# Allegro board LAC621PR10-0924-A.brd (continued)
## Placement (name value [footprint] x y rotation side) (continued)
RL34  -  [R0402_0OHM]  257.77 83.57 90 top
RL70  -  [R_0402]  261.12 90.07 270 bottom
RL71  -  [R_0603]  261.68 80.3 270 top
RL72  -  [R_0603]  263.03 80.32 270 top
RL73  -  [R_0603]  264.4 80.32 270 top
RL74  -  [R_0603]  265.8 80.34 270 top
RL75  -  [R_0603]  267.17 80.32 270 top
RL76  -  [R_0603]  268.54 80.32 270 top
RL77  -  [R_0603]  269.12 81.46 0 top
RL78  -  [R_0603]  269.12 82.86 0 top
RN1  -  [R_0402]  278.6 20.02 0 top
RN2  -  [R_0402]  281.93 16.72 180 top
RN5  -  [R_0402]  275.35 18.75 0 top
RN6  -  [R_0402]  265.27 34.03 180 top
RN7  -  [R_0402]  264.36 33.14 0 top
RN8  -  [R_0402]  266.74 20.4 180 top
RN9  -  [R_0402]  266.74 21.29 180 top
RN10  -  [R_0402]  265.82 18.62 0 top
RN11  -  [R_0402]  266.74 19.51 180 top
RN12  -  [R_0402]  261.87 30.21 90 top
RN13  -  [R_0402]  261.87 28.18 90 top
RN14  -  [R_0402]  259.91 31.12 270 top
RN16  -  [R_0402]  259.91 28.18 90 top
RN18  -  [R_0402]  264.37 17.66 90 top
RN19  -  [R_0402]  263.49 17.66 90 top
RN20  -  [R_0402]  262.88 31.12 270 top
RN21  -  [R_0402]  262.88 28.18 90 top
RN22  -  [R_0402]  275.35 19.64 0 top
RN23  -  [R_0402]  277.14 19.31 270 top
RN25  -  [R_0402]  228.05 37.72 90 top
RN26  -  [R_0402]  224.42 31.88 0 top
RN27  -  [R_0402]  225.23 25.13 90 top
RN28  -  [R_0402]  222.64 30.05 0 top
RN30  -  [R_0402]  225.31 29.14 180 top
RN31  -  [R_0402]  237.12 29.02 180 top
RN37  -  [R_0402]  255.79 11.07 0 top
RN38  -  [R_0402]  227.16 34.29 90 top
RN39  -  [R_0402]  225.31 30.97 180 top
RN40  -  [R_0402]  226.12 26.04 270 top
RN41  -  [R_0402]  225.31 30.03 180 top
RN42  -  [R_0402]  235.04 31.65 270 top
RN43  -  [R_0402]  233.97 29.04 180 top
RN44  -  [R_0402]  233.36 25.13 90 top
RN45  -  [R_0402]  233.06 30.81 0 top
RN46  -  [R_0402]  233.06 29.93 0 top
RN47  -  [R_0402]  232.47 26.04 270 top
RN49  -  [R_0402]  223.48 28.48 270 top
RN50  -  [R_0402]  233.97 27.26 180 top
RN51  -  [R_0402]  228.79 25.13 90 top
RN52  -  [R_0402]  225.31 28.2 180 top
RN53  -  [R_0402]  233.06 28.15 0 top
RN54  -  [R_0402]  229.67 26.04 270 top
RN55  -  [R_0402]  237.7 34.07 270 top
RN56  -  [R_0402]  235.95 31.68 0 top
RN57  -  [R_0402]  237.17 24.11 90 top
RN58  -  [R_0402]  236.2 30.79 0 top
RN59  -  [R_0402]  238.59 33.15 90 top
RN60  -  [R_0402]  236.82 33.15 90 top
RN61  -  [R_0402]  238.31 25.03 270 top
RN62  -  [R_0402]  237.12 29.9 180 top
RN63  -  [R_0402]  244.84 32.32 0 top
RN64  -  [R_0402]  245.75 29.65 180 top
RN65  -  [R_0402]  244.84 25.97 0 top
RN66  -  [R_0402]  244.84 31.43 0 top
RN67  -  [R_0402]  244.84 30.54 0 top
RN68  -  [R_0402]  244.84 26.86 0 top
RN69  -  [R_0402]  236.2 27.24 0 top
RN70  -  [R_0402]  245.75 28.76 180 top
RN71  -  [R_0402]  241.87 24.11 90 top
RN72  -  [R_0402]  237.12 28.13 180 top
RN73  -  [R_0402]  244.84 27.87 0 top
RN74  -  [R_0402]  240.98 25.03 270 top
RN77  -  [R_0402]  227.01 25.13 90 top
RN78  -  [R_0402]  227.9 25.13 90 top
RN81  -  [R_0402]  239.2 24.11 90 top
RN82  -  [R_0402]  240.09 24.11 90 top
RN83  -  [R_0402]  260.87 29.11 270 top
RN84  -  [R_0402]  260.98 31.12 270 top
RN99  -  [R0402_0OHM]  249.82 10.75 0 top
RPC1  -  [RP_0804_8P4R]  194.89 65.04 90 bottom
RPC2  -  [RP_0804_8P4R]  192.51 52.21 90 top
RPC3  -  [RP_0804_8P4R]  175.97 82.56 90 bottom
RPC4  -  [RP_0804_8P4R]  184.17 72.38 270 bottom
RPC5  -  [RP_0804_8P4R]  183.91 69.52 180 bottom
RPE2  -  [RP_0804_8P4R]  258.91 70.31 270 top
RPE3  -  [RP_0804_8P4R]  259.12 49.51 270 top
RPE5  -  [RP_0804_8P4R]  277.61 59.23 0 top
RPE7  -  [RP_0804_8P4R]  296.52 41.62 180 top
RPE8  -  [RP_0804_8P4R]  242.09 82.64 180 top
RPE9  -  [RP_0804_8P4R]  253.69 73.55 270 top
RPE10  -  [RP_0804_8P4R]  277.61 62.15 0 top
RPE11  -  [RP_0804_8P4R]  242.4 74.5 0 top
RPE12  -  [RP_0804_8P4R]  263.87 75.65 270 top
RPE13  -  [RP_0804_8P4R]  264.09 48.14 90 top
RPV1  -  [RP_0804_8P4R]  223.93 95.05 0 top
RPV2  -  [RP_0804_8P4R]  205.73 87.63 180 top
RR1  -  [R_0402]  259.8 37.88 270 top
RR16  -  [R_0402]  267.3 41.61 180 top
RR17  -  [R0402_0OHM]  262.47 37.88 270 top
RR18  -  [R0402_0OHM]  263.36 37.88 270 top
RR19  -  [R_0402]  267.3 42.5 180 top
RR20  -  [R_0402]  259.17 45.47 90 top
RR21  -  [R0402_0OHM]  258.86 38.69 180 top
RR22  -  [R0402_0OHM]  258.86 37.8 180 top
RR23  -  [R0402_0OHM]  261.58 37.88 270 top
RV1  -  [R_0402]  86.42 85.91 90 top
RV2  -  [R_0402]  85.56 85.91 90 top
RV3  -  [R_0402]  99.02 82.1 270 bottom
RV4  -  [R_0402]  88.89 79.15 0 bottom
RV5  -  [R_0402]  91.55 80.09 270 bottom
RV6  -  [R_0402]  96.35 98.17 90 top
RV8  -  [R_0402]  93.15 98.94 270 top
RV10  -  [R_0402]  81.32 95.65 180 top
RV11  -  [R_0402]  82.18 95.65 0 top
RV12  -  [R_0402]  84.16 94.75 180 top
RV13  -  [R_0402]  85.03 94.75 0 top
RV14  -  [R_0402]  89.65 94.72 180 top
RV15  -  [R_0402]  90.51 94.72 0 top
RV16  -  [R_0402]  86.91 95.61 180 top
RV17  -  [R_0402]  87.77 95.61 0 top
RV18  -  [R_0402]  106.06 94.59 180 bottom
RV19  -  [R_0402]  78.95 99.09 270 top
RV20  -  [R_0402]  94.53 99.22 0 top
RV21  -  [R_0402]  106.08 95.53 180 bottom
RV22  -  [R_0402]  91.38 93.82 0 top
RV32  -  [R_0402]  232.8 94.67 180 bottom
RV33  -  [R_0402]  234.3 94.67 0 bottom
RV34  -  [R_0402]  236.71 94.55 0 bottom
RV35  -  [R_0402]  236.36 103.2 0 bottom
RV36  -  [R_0402]  247.15 103.18 180 bottom
RV37  -  [R_0402]  242.66 100.84 90 bottom
RV38  -  [R_0402]  240.88 100.84 90 bottom
RV73  -  [R_0402]  228.99 84.61 0 top
RV74  -  [R_0402]  210.15 92.89 0 top
RV75  -  [R_0402]  217.92 94.68 180 bottom
RV76  -  [R_0402]  231.66 88.19 270 top
RV77  -  [R_0402]  232.55 88.19 270 top
RV78  -  [R_0402]  234.73 88.24 270 top
RV79  -  [R_0402]  210.98 84.41 180 top
RV80  -  [R_0402]  223.3 82.42 90 top
RV81  -  [R_0402]  223.3 85.09 270 top
RV82  -  [R_0402]  220.1 94.7 0 bottom
RV83  -  [R_0402]  212.74 82.58 270 top
RV84  -  [R_0402]  210.98 83.49 180 top
RV85  -  [R_0402]  209.28 92.89 180 top
RV86  -  [R_0402]  206.97 92.23 270 top
RV87  -  [R_0402]  207.17 90.4 0 bottom
RV88  -  [R_0402]  229.91 85.5 180 top
RV89  -  [R_0402]  229.51 87.32 0 top
RV90  -  [R_0402]  125.31 89.41 180 bottom
RV91  -  [R_0402]  146.31 92.13 180 bottom
RV121  -  [R_0402]  235.62 87.33 90 top
RV250  -  [R_0402]  236.51 87.33 90 top
RV251  -  [R_0402]  238.11 87.33 90 top
RV508  -  [R_0402]  132.75 92.13 180 bottom
RV509  -  [R_0402]  141.49 87.46 0 bottom
RV516  -  [R_0402]  208.44 84.54 180 top
RV517  -  [R_0402]  208.32 83.49 0 top
RV518  -  [R_0402]  210.4 96.78 0 top
RV519  -  [R_0402]  210.41 95.91 0 top
RV600  -  [R_0402]  201.56 89.54 180 bottom
RV601  -  [R_0402]  186.83 88.6 0 bottom
RV602  -  [R_0402]  199.86 91.32 270 bottom
RV603  -  [R_0402]  186.32 90.63 0 bottom
RV604  -  [R_0402]  201.89 83.65 180 bottom
RV605  -  [R_0402]  201.94 81.39 180 bottom
RV606  -  [R_0402]  193.31 80.57 90 bottom
RV607  -  [R_0402]  199.05 79.85 180 bottom
RV608  -  [R_0402]  201.89 84.76 180 bottom
RV609  -  [R_0402]  201.89 82.73 180 bottom
RV610  -  [R_0402]  191.02 94.3 270 bottom
RV611  -  [R_0402]  185.08 85.15 0 bottom
RV612  -  [R_0402]  185.08 86.04 0 bottom
RV613  -  [R_0402]  185.08 87.18 0 bottom
RV614  -  [R_0402]  185.08 88.07 0 bottom
RV615  -  [R_0402]  186.32 89.62 0 bottom
RV616  -  [R_0402]  192.67 90.44 90 bottom
RV617  -  [R_0402]  186.86 84.64 0 bottom
RV618  -  [R_0402]  186.86 85.53 0 bottom
RV619  -  [R_0402]  186.86 86.67 0 bottom
RV620  -  [R_0402]  186.86 87.56 0 bottom
RV621  -  [R_0402]  187.24 91.52 180 bottom
RV623  -  [R_0402]  82.76 83.06 90 bottom
RV647  -  [R_0402]  81.27 97.09 90 top
RV648  -  [R_0402]  82.19 99.18 180 top
RV649  -  [R_0402]  82.13 97.09 90 top
RV650  -  [R_0402]  84.12 97.07 90 top
RV651  -  [R_0402]  85 99.18 180 top
RV652  -  [R_0402]  84.98 97.07 90 top
RV653  -  [R_0402]  89.63 97.02 90 top
RV654  -  [R_0402]  90.47 99.18 180 top
RV655  -  [R_0402]  90.49 97.02 90 top
RV656  -  [R_0402]  86.93 97.04 90 top
RV657  -  [R_0402]  87.82 99.18 180 top
RV658  -  [R_0402]  87.8 97.04 90 top
RV659  -  [R_0402]  234.66 96.57 180 top
RV660  -  [R_0402]  233.75 97.46 0 top
RV661  -  [R_0402]  234.67 95.66 180 top
RV662  -  [R0402_0OHM]  227.18 94.55 90 top
RZ8  -  [R_0402]  266.79 13.8 0 top
RZ9  -  [R_0402]  266.79 12.91 0 top
RZ10  -  [R_0402]  260.56 12.35 270 top
RZ18  -  [R_0402]  220.47 35.9 180 top
RZ19  -  [R_0402]  220.47 35.02 180 top
RZ20  -  [R_0402]  221.11 32.59 180 top
RZ21  -  [R_0402]  220.29 34.15 180 top
RZ22  -  [R0402_0OHM]  217.5 36.78 0 top
RZ23  -  [R0402_0OHM]  217.43 35.73 0 top
RZ24  -  [R_0402]  287.47 71.09 180 bottom
RZ25  -  [R_0402]  264.76 54.44 270 top
RZ26  -  [R_0402]  220.21 31.66 0 top
RZ27  -  [R_0402]  284.49 75.9 0 bottom
RZ28  -  [R_0402]  275.2 58.42 180 top
RZ29  -  [R_0402]  217.51 33.5 0 top
RZ32  -  [R_0402]  288.33 71.08 0 bottom
RZ34  -  [R_0402]  288.81 66.88 180 bottom
RZ38  -  [R_0402]  252.69 42.88 180 top
RZ40  -  [R_0402]  247.23 47.07 90 top
RZ43  -  [R0402_0OHM]  241.11 76.15 0 top
RZ56  -  [R0402_0OHM]  257.01 19.64 90 top
RZ58  -  [R_0402]  186.86 74.44 270 top
RZ59  -  [R_0402]  189.19 75.31 90 top
RZ60  -  [R_0402]  190.97 75.21 270 top
RZ61  -  [R0402_0OHM]  189.3 72.74 270 top
RZ62  -  [R_0402]  185.76 68.99 90 top
RZ63  -  [R_0402]  190.08 75.21 270 top
RZ64  -  [R0402_0OHM]  246.29 45.42 180 top
RZ65  -  [R_0402]  246.29 46.31 180 top
RZ69  -  [R_0402]  194.91 76.47 180 top
RZ70  -  [R0402_0OHM]  251.04 41.81 270 top
RZ71  -  [R_0402]  250.15 41.81 270 top
RZ72  -  [R_0603]  188.92 61.28 90 top
RZ76  -  [R_0402]  237.32 68.03 0 top
RZ77  -  [R_0402]  237.32 67.14 0 top
RZ78  -  [R_0402]  257.9 19.69 90 top
RZ79  -  [R_0402]  258.79 19.69 90 top
RZ80  -  [R_0402]  258.06 29.09 270 top
RZ81  -  [R_0402]  258.95 29.09 270 top
RZ82  -  [R_0402]  173.54 90.63 0 bottom
RZ83  -  [R_0402]  173.54 91.52 0 bottom
RZ84  -  [R_0402]  272.96 10.75 180 top
RZ85  -  [R0402_0OHM]  275.14 10.77 180 top
RZ86  -  [R0402_0OHM]  263.52 11.67 270 top
RZ87  -  [R_0402]  257.8 15.31 180 top
RZ88  -  [R_0402]  190.82 63.52 0 top
RZ89  -  [R0402_0OHM]  192.09 61.66 180 top
RZ90  -  [R_0402]  185.13 67.76 270 top
RZ110  -  [R_0402]  196.74 68.24 270 top
RZ111  -  [R_0402]  193.64 61.99 270 top
RZ112  -  [R0402_0OHM]  185.68 65.96 180 top
RZ113  -  [R_0402]  196 66.12 270 top
RZ114  -  [R_0402]  263.66 15.18 90 top
RZ115  -  [R_0402]  262.77 15.18 90 top
RZ116  -  [R_0402]  218.44 31.68 0 top
RZ117  -  [R_0402]  218.43 32.57 180 top
RZ118  -  [R0402_0OHM]  266.98 16.39 270 top
RZ119  -  [R_0603]  157.88 42.22 0 top
RZ120  -  [R_0402]  163.06 38.11 180 top
SW1  -  [SW_SS3-CMFTQR9_3P]  247.51 97.44 270 bottom
SW3  -  [SW_SKRBAAE010_4P]  300 84.76 0 top
T1  -  [TPC12]  146.47 85.33 0 top
T2  -  [TPC12]  146.5 72.58 0 top
T3  -  [TPC12]  140.6 59.19 0 top
T4  -  [TPC12]  139.56 45.24 0 top
T5  -  [TPC12]  143.02 61.05 0 top
T6  -  [TPC12]  143.27 59.59 0 top
T9  -  [TPC12]  121.38 87.19 180 bottom
T10  -  [TPC12]  142.51 81.68 180 bottom
T11  -  [TPC12]  140.76 81.83 180 bottom
T12  -  [TPC12]  122.49 44.39 0 top
T13  -  [TPC12]  124.14 44.43 0 top
T14  -  [TPC12]  166.07 61.68 0 top
T15  -  [TPC12]  168.46 62.14 0 top
T16  -  [TPC12]  125.28 45.19 0 top
T17  -  [TPC12]  129 45.96 0 top
T50  -  [TPC12]  120.81 14.51 0 top
T51  -  [TPC12]  123.28 15.45 0 top
T54  -  [TPC12]  203.19 14.75 0 top
T55  -  [TPC12]  201.89 15.27 0 top
T87  -  [TPC12]  233.82 103.29 180 bottom
T88  -  [TPC12]  268.6 84.27 0 top
T89  -  [TPC12]  268.6 86.35 0 top
T97  -  [TPC12]  246.37 84.69 180 bottom
T98  -  [TPC12]  252.77 90.8 0 top
T99  -  [TPC12]  246.34 89.23 0 top
T108  -  [TPC12]  229.1 88.74 0 top
T113  -  [TPC12]  126.33 46.04 0 top
T114  -  [TPC12]  127.68 45.99 0 top
T115  -  [TPC12]  167.98 59.57 0 top
T120  -  [TPC12]  166.76 70.26 0 top
T121  -  [TPC12]  180.79 45.63 0 top
T122  -  [TPC12]  156.3 69.73 0 top
T123  -  [TPC12]  155.73 63.2 0 top
T126  -  [TPC12]  191 49.19 180 bottom
T127  -  [TPC12]  193.25 49.1 180 bottom
T128  -  [TPC12]  180.15 57.86 180 bottom
T129  -  [TPC12]  178.5 58.33 180 bottom
T130  -  [TPC12]  182.11 46.24 90 top
T131  -  [TPC12]  273.09 60.63 0 top
T132  -  [TPC12]  130.49 46.08 0 top
TL1  -  [MHPC_NS692417_24P]  279.99 85.81 180 bottom
UA1  -  [ALC3235-CG_MQFN48_6X6]  276.06 35.68 270 top
UC1  -  [SKL-U_BGA_1356P-T]  173.35 77.16 0 bottom
UC5  -  [W25Q128FVSIQ_SO8]  191.1 75.46 0 bottom
UC6  -  [W25Q64FVSSIQ_SO8]  191.1 59.97 0 bottom
UC7  -  [TC7SH08FU_SSOP5]  187.65 67.94 270 bottom
UC8  -  [74CBTLV3126BQ_DHVQFN14_2P5X3]  99.2 42.57 0 top
UC12  -  [74AHC1G09GW_TSSOP5]  180.06 90.08 0 bottom
UC13  -  [TC7SH08FU_SSOP5]  172.2 92.26 270 bottom
UC14  -  [TC7SH08FU_SSOP5]  188.31 30.3 0 top
UD1  -  [74AUP1G07GW_TSSOP5]  77.43 13.9 180 top
UE1  -  [ECE5048-LZY_DQFN132_11X11]  253.39 88.08 180 top
UE2  -  [MEC5085-LZY_DQFN132_11X11]  271.35 57.54 90 top
UE3  -  [TC7SH08FU_SSOP5]  227.22 76.57 0 top
UE4  -  [74AUP1G07GW_TSSOP5]  225.92 79.09 180 top
UE5  -  [TC7SH08FU_SSOP5]  254.72 64.99 0 top
UI1  -  [SY6288D20AAC_SOT23-5]  19.38 90.59 0 bottom
UI2  -  [SY6288D20AAC_SOT23-5]  72.48 92.41 180 top
UI3  -  [PI5USB2544ZHEX_TQFN16_3X3]  281.49 64.33 0 top
UL1  -  [WGI217LM-QPN9-A2_QFN48_6X6]  261.12 89.13 270 top
UL2  -  [TC7SH08FU_SSOP5]  282.51 73.06 180 bottom
UL4  -  [PI3L720ZHEX_TQFN42_9X3P5]  273.42 82.72 270 top
UN1  -  [LNG2DMTR_LGA12_2X2]  252.69 32.59 0 top
UN4  -  [PS8558BTQFN24GTR2-A_TQFN24_4X4]  230.54 32.21 270 top
UN5  -  [PS8558BTQFN24GTR2-A_TQFN24_4X4]  241.87 31.17 270 top
UN7  -  [PI3EQX6741STZDEX_TQFN20_4X4]  260.15 25.44 0 top
UR2  -  [RTS5242-GR_QFN32_4X4]  263.92 43.69 270 top
UV2  -  [AP2330W-7_SC59-3]  103.01 94.03 0 bottom
UV4  -  [AP2330W-7_SC59-3]  244.51 100.41 270 bottom
UV8  -  [VMM3320BJGR_BGA_168P-NH]  213.91 85.24 90 top
UV9  -  [W25X10BVSNIG_SO8]  211.46 88.09 270 bottom
UV11  -  [PI3C3125LEX_TSSOP14]  121.34 90.69 90 bottom
UV12  -  [PI3C3125LEX_TSSOP14]  147.98 84.66 180 bottom
UV16  -  [PI3V713-AZLEX_TQFN32_6X3]  233.01 90.04 0 top
UV24  -  [G524B1T11U_SOT23-5]  94.91 81.45 0 bottom
UV26  -  [PS8338BQFN60GTR-A0_QFN60_5X9]  190.65 88.01 0 bottom
UV28  -  [TPS22961DNYR_WSON8]  227.19 95.18 0 bottom
UV29  -  [APL5930QBI-TRG_TDFN10_3X3]  232.16 95.75 90 top
UZ2  -  [TPS22966DPUR_SON14_2X3]  246.66 49.22 0 top
UZ3  -  [TPS22966DPUR_SON14_2X3]  251.22 39.26 180 top
UZ4  -  [TPS22966DPUR_SON14_2X3]  243.94 45.24 90 top
UZ5  -  [TPS22966DPUR_SON14_2X3]  273.99 44.92 0 top
UZ6  -  [TC7SH08FU_SSOP5]  220.62 29.28 90 top
UZ8  -  [AOZ1336_DFN8_2X2]  248.8 45.06 180 top
UZ10  -  [TC7SH08FU_SSOP5]  288.81 65.51 180 top
UZ12  -  [NPCT650JAAYX_QFN32_5X5]  187.9 64.87 90 top
UZ19  -  [TPS22961DNYR_WSON8]  167.68 93 270 bottom
UZ20  -  [TPS22961DNYR_WSON8]  168.81 86.7 90 bottom
UZ21  -  [TPS22961DNYR_WSON8]  165.36 88.55 0 bottom
UZ23  -  [AOZ1336_DFN8_2X2]  265.54 31.82 180 top
UZ26  -  [TPS22961DNYR_WSON8]  159.03 38.23 0 top
YC1  -  [Y_X3G024000DC1H_4P]  154.22 84.32 180 bottom
YC2  -  [Y_9H03200042_2P]  182.79 61.98 270 bottom
YE1  -  [Y_Q13FC135000040_2P]  266.54 51.22 0 top
YL1  -  [Y_7V25000034_4P]  259.48 79.94 90 top
YV2  -  [Y_X1E000021042600_4P]  227.01 82.42 90 top

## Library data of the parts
C33 CC210 CC219-CC221 CC225 CC226 CC271-CC274 CL28 PC5 PC7 PC104-PC110 PC117 PC118 PC120-PC124 PC201 PC202 PC305 PC306 PC308-PC311 PC508 PC511 PC608 PC612 PC656-PC658 PC672 PC673 PC801 PC803-PC807 PC811 PC812 PC814 PC818-PC820 PC822 PC826 PC827 PC902 PC1501 PC1503 = C_0805
C42 C43 C263 C294-C316 C319 CA1-CA6 CA12 CA13 CA19 CA22-CA24 CA27 CA28 CA33 CA35 CA41 CA54 CC3-CC8 CC21-CC27 CC32 CC33 CC174-CC179 CC181 CC182 CC185 CC186 CC194 CC195 CC199 CC202-CC204 CC206 CC208 CC209 CC211-CC213 CC215-CC218 CC222 CC224 CC248-CC257 CC264 CC266 CC269 CC288 CC297 CC300-CC302 CC310 CC311 CD2-CD4 CD6-CD11 CD24-CD27 CD31 CD35-CD44 CD54 CD57-CD60 CD63 CD70 CD71 CD74 CD75 CD78-CD85 CD102-CD109 CE8-CE10 CE12 CE14 CE15 CE24 CE26-CE30 CE34-CE40 CE44-CE47 CE52 CE53 CI4 CI5 CI13 CI16 CI27-CI31 CI33-CI35 CL1 CL2 CL5 CL6 CL13 CL14 CL18 CN13 CN17 CN18 CN20-CN26 CN30-CN36 CN43-CN48 CN50 CR23-CR27 CR35 CR37 CR42 CR43 CV1-CV6 CV10 CV11 CV13 CV14 CV17 CV18 CV21 CV22 CV28 CV29 CV50-CV59 CV79 CV80 CV85 CV86 CV89 CV92 CV93 CV96-CV99 CV102-CV111 CV113 CV115 CV119 CV120 CV122 CV123 CV127 CV128 CV145-CV150 CV152 CV153 CV156 CV157 CV374 CV603-CV613 CV616 CV619 CZ13 CZ14 CZ16 CZ20-CZ23 CZ30 CZ31 CZ37 CZ38 CZ42 CZ45 CZ46 CZ51-CZ53 CZ55 CZ58 CZ59 CZ65-CZ69 CZ77 CZ84 CZ87 CZ90 CZ91 CZ95 CZ100 CZ105 CZ106 CZ113 PC3 PC4 PC8 PC100 PC101 PC103 PC113 PC115 PC116 PC127 PC128 PC203 PC204 PC210 PC212-PC214 PC301 PC303 PC307 PC401 PC402 PC408-PC411 PC417-PC420 PC503 PC505-PC507 PC509 PC510 PC601 PC602 PC605 PC613 PC614 PC616-PC621 PC624-PC633 PC636 PC637 PC639-PC647 PC649-PC654 PC659-PC661 PC677 PC679 PC680 PC685 PC686 PC688 PC809 PC810 PC815-PC817 PC823 PC824 PC829-PC831 PC833 PC834 PC901 PC903-PC905 PC1500 PC1502 PC1504 = C_0402
C317 C318 CA9 CA10 CA16 CA18 CA25 CA26 CA29 CA31 CA43 CA44 CA46 CA48 CA49 CA51-CA53 CC279 CC280 CC282-CC287 CC294-CC296 CD12-CD19 CD28 CD29 CD45-CD52 CD61 CD62 CD72 CD73 CD76 CD77 CD86-CD101 CE1 CE7 CE21 CE31 CE32 CI6 CI11 CL4 CL12 CN1 CR9 CR38 CR40 CV7 CV9 CV12 CV27 CV82 CV87 CV90 CV94 CV101 CV617 CV618 CZ19 CZ54 CZ60 CZ61 CZ72 CZ76 PC1 PC2 PC6 PC102 PC111 PC112 PC114 PC119 PC125 PC126 PC205-PC207 PC209 PC211 PC215-PC220 PC302 PC304 PC312 PC313 PC403 PC404 PC406 PC407 PC412 PC413 PC415 PC416 PC422 PC424 PC501 PC502 PC504 PC603 PC604 PC611 PC622 PC655 PC662 PC671 PC678 PC802 PC808 PC813 PC821 PC825 PC828 PC832 PC906-PC908 PC1001-PC1029 PC1057-PC1061 PC1064-PC1082 PC1129-PC1146 PC1170-PC1181 = C_0603
CA7 CA8 CA11 CA17 CA45 CA47 CA50 CC9 CC10 CC28-CC30 CC214 CC223 CC270 CC281 CD30 CD32 CD64 CE2-CE6 CE11 CE13 CE16-CE20 CE22 CE23 CE25 CI3 CI7 CI10 CI12 CI17 CI19 CL3 CL7-CL11 CL15-CL17 CL19-CL21 CL25-CL27 CN2 CN14-CN16 CN19 CN29 CN41 CN42 CN49 CR8 CR10 CR13 CR36 CR39 CR41 CV8 CV23 CV26 CV83 CV84 CV88 CV91 CV95 CV100 CV114 CV118 CV121 CV124-CV126 CV144 CV600-CV602 CV615 CZ1 CZ2 CZ10-CZ12 CZ15 CZ17 CZ18 CZ24 CZ27-CZ29 CZ34 CZ36 CZ39 CZ43 CZ44 CZ47 CZ48 CZ50 CZ64 CZ71 CZ73-CZ75 CZ78 CZ82 CZ85 CZ89 CZ92 CZ94 CZ99 CZ114 CZ115 PC1030-PC1056 PC1083-PC1099 PC1125 PC1126 PC1147-PC1153 PC1164 = C_0201
CD20 CD53 = C_D3
CI1 CI8 CI14 = C_1206
CI32 = C_B2-NPM
CL22 = C_1808
CMOS1 = SHORTPADS-NPM: User Part Number: PART#
CZ57 = C_B2
D19 DA4 DA5 DE1 DZ1-DZ7 = RB751S40T1G_SOD523-2
D20 = L30ESD24VC3-2_SOT23-3
DA1-DA3 DA6 DA7 = L03ESDL5V0CC3-2_SOT23-3
DI1 DI4 DI6 = L05ESDL5V0NA-4_SLP2510P8-10-9
DI2 DI3 DI5 DV4 = AZC199-02SPR7G_SOT23-3
DV1-DV3 PD901 PD905 = BAT54CW_SOT323-3
DV5 DV6 = PJDLC05C_SOT23-3
FD1-FD4 = FIDUCIAL_C40M80
H1-H4 H25 = H_3P8
H5 = H_2P6N
H6 = H_3P0X2P0N
H7 H8 = H_3P2
H9 = H_0P9N
H10 = H_0P8N
H11-H22 H24 = H_2P4
H23 = H_3P3
JAPS1 = ACES_50506-01841-P01_18P-NPM
JCRT1 = FUTUR_061-D531-0207_15P
JDEG1 JLPDE1 = HB_A531015-SCHR21_10P
JDIMM1 JDIMM2 = LOTES_ADDR0107-P005A_260P-T
JDOCK1 = JAE_WD2F144WB5R400_144P
JEDP1 = ACES_50398-04041-001_40P
JFAN1 JSPK1 = ACES_50271-0040N-001_4P
JHDMI1 = CONCR_099BKAC19YBLCNF_19P
JHP1 = SINGA_2SJ3095-022111F_6P-T
JIR1 = ACES_50450-0067N-P01_6P
JKBTP1 = ACES_50506-02041-P01_20P
JLED1 = ACES_50506-00841-P01_8P
JLOM1 = SANTA_130456-511_13P-T
JNGFF1 = BELLW_80148-4221_67P
JNGFF2 = BELLW_80149-4221_67P
JNGFF3 = BELLW_SD-80159-4221_67P-T
JRTC1 = ACES_50271-0020N-001_2P
JSATA1 = STARC_115B20-100020-G2-R_20P
JSD1 = T-SOL_156-2000302608_19P_NR
JSIM1 = T-SOL_5-991503004000-6_8P-T
JSPI1 = E-T_6705K-Y20N-00L_20P
JTAG1 = SHORTPADS: User Part Number: PART#
JUART1 = ACES_50207-00471-P01_4P-T
JUSB1 = LOTES_AUSB0014-P003A_9P
JUSB2 = ACON_TARAV-9R1U91_9P
JUSB3 = SINGA_2UB4008-900101F_9P
JUSH1 = E-T_6705K-Y26N-00L_26P
JXDP1 = SAMTE_BSH-030-01-L-D-A_60P
LA2 LA3 = MURAT_BLM15BD601SN1D_2P
LA5 LC1 LC2 = MURAT_BLM15PX600SN1D_2P
LA6-LA11 = MURAT_BLM15PX330SN1D_2P
LED3 = LED_LTW-C193DC-C_2P
LI3 LI4 LI7 LV27 LZ1 = INPAQ_MCM1012B900F06BP_4P
LL1 = TAIYO_BRC2012T4R7MD_2P
LV1 = MURAT_BLM15BB221SN1D_2P
LV16-LV18 = MURAT_BLM15BB470SN1D_2P
LV19 LV20 = MURAT_BLM15AG121SN1D_L0402_2P
LV22-LV25 = MURAT_BLM15PX181SN1D_2P
PBATT1 = DEREN_40-42251-01001RHF_10P-T
PC606 = C_D
PC1062 PC1063 PC1127 PC1128 = C_D2
PD1 = DB3J315E0L_SMINI3-F2-B3
PD2 PD3 = TVNST52302AB0_SOT523-3
PD4 = RB751V-40_SOD323-2
PD6 PD7 = PESD5V0U2BT_SOT23-3
PD801-PD803 PD904 = SDMK0340L-7-F_SOD323-2
PD902 PD903 = PDS5100H-13_POWERDI5-3
PH601-PH605 PR1-PR3 PR5-PR12 PR14 PR15 PR101-PR103 PR107-PR110 PR113 PR115-PR118 PR203 PR206 PR207 PR209 PR302 PR306-PR308 PR310 PR311 PR403 PR404 PR407 PR408 PR410 PR411 PR413-PR421 PR424-PR426 PR428 PR501 PR505-PR511 PR601 PR604 PR605 PR608 PR610-PR613 PR617 PR618 PR621-PR623 PR626 PR628-PR633 PR635 PR636 PR638-PR652 PR656 PR657 PR662 PR678 PR680 PR801 PR803 PR805 PR808 PR809 PR812 PR813 PR817 PR818 PR821 PR822 PR825 PR827 PR829-PR832 PR834 PR837 PR902-PR905 PR908-PR912 PR914-PR917 PR920 PR925 PR927 PR929 PR934 PR936 PR1500-PR1503 R6 R41 R252-R268 R271-R273 RA1 RA2 RA5-RA9 RA12-RA14 RA17 RA18 RA21 RA24-RA32 RA38 RA44 RC1-RC7 RC10-RC36 RC38-RC40 RC42-RC48 RC50-RC52 RC54 RC56 RC57 RC59 RC60 RC65 RC67-RC69 RC71-RC84 RC86-RC96 RC109 RC110 RC112-RC115 RC120-RC124 RC126 RC128-RC141 RC152 RC153 RC157 RC161 RC163 RC165-RC168 RC175-RC184 RC186 RC187 RC189 RC190 RC212 RC215 RC217-RC220 RC222-RC225 RC227 RC234 RC236 RC237 RC239-RC243 RC246 RC267 RC268 RC270 RC272 RC276 RC279 RC281-RC283 RC287 RC288 RC291 RC292 RC297 RC298 RC311-RC313 RC316-RC320 RC322-RC324 RC326 RC330 RC331 RC335 RC336 RC338-RC344 RC346-RC348 RD2 RD4 RD18-RD22 RD24 RD25 RD30 RD61-RD64 RD69 RD71 RD73 RD75 RE11 RE12 RE17 RE20 RE21 RE24-RE27 RE31 RE33 RE35 RE36 RE38 RE42 RE48 RE51 RE55-RE58 RE60 RE62-RE75 RE77-RE79 RE81-RE86 RE88 RE90 RE274 RE277 RE280 RE288 RE292 RE298-RE301 RE304 RE306 RE308-RE313 RH359 RI13 RI14 RL1 RL2 RL4-RL6 RL9 RL11-RL20 RL29 RL30 RL70 RN1 RN2 RN5-RN14 RN16 RN18-RN23 RN25-RN28 RN30 RN31 RN37-RN47 RN49-RN74 RN77 RN78 RN81-RN84 RR1 RR16 RR19 RR20 RV1-RV6 RV8 RV10-RV22 RV32-RV38 RV73-RV91 RV121 RV250 RV251 RV508 RV509 RV516-RV519 RV600-RV621 RV623 RV647-RV661 RZ8-RZ10 RZ18-RZ21 RZ24-RZ29 RZ32 RZ34 RZ38 RZ40 RZ58-RZ60 RZ62 RZ63 RZ65 RZ69 RZ71 RZ76-RZ84 RZ87 RZ88 RZ90 RZ110 RZ111 RZ113-RZ117 RZ120 = R_0402
PJP6 PJP10 PJP11 PJP13-PJP16 PJP19 PJP20 PJP24 PJP25 PJP27 PJP29 PJP30 PJP32 PJP33 PJP203 PJP205 PJP403 PJP404 PJP503 PJP504 PJP603 PJP805 PJP1500 PJP1501 PJP1603 = JUMP_43X39
PJP9 PJP22 PJP23 PJP31 PJP35 PJP102 PJP103 PJP201 PJP204 PJP302 PJP601 = JUMP_43X118
PJP12 PJP21 PJP26 PJP34 PJP36 PJP100 PJP101 PJP202 PJP301 PJP401 PJP402 PJP501 PJP502 PJP602 = JUMP_43X79
PJP801 = JUMP_43X118-NPM
PJPDC1 = ACES_50290-0050N-001_5P-T
PL1-PL3 = TAIYO_FBMJ4516HS720NT_2P
PL4 = MURAT_BLM15AG102SN1D_2P
PL100 PL101 = CYNTE_PCMC063T-1R5MN_2P
PL201 = CYNTE_PCMB063T-1R0MS_2P
PL301 = MAG_MMD-05CZ-R68M-X2L_2P
PL402 PL404 PL501 = MAG_MLV-FY12N1R0M-O1L_2P
PL601 PL802 = MAGLA_MMD-05CZ-1R0M-M7L_2P
PL602 = KC_FBMA-L11-4532158_2P-NPM
PL603 PL604 = MAG_MMD06CZER15MG_4P
PL801 = CYNTE_PCMB063T-3R3MS_2P
PQ1 = IMD2AT-108_SC74-6
PQ2 PQ909 = SI2301CDS-T1-GE3_SOT23-3
PQ3 = FDV301N-G_SOT23-3
PQ4 = MMST3904-7-F_SOT323-3
PQ5 PQ905 = FDMC6679AZ_MLP8-5
PQ201 PQ808 = AON6932A_DFN5X6-8-7
PQ501 = AON7934_DFN3X3A8-10
PQ801 PQ803-PQ805 = NTR4502PT1G_SOT23-3
PQ802 PQ903 = SI4835DDY-T1-GE3_SO8
PQ809 PQ906 PQ908 = DMN65D8LW-7_SOT323-3
PQ901 PQ904 = FDS6679AZ-G_SO8
PQ902 PQ907 PQ911 QA2 QA3 QC2 QE2 QL1 QL2 QN1 QV3 QZ3 QZ7 = DMN65D8LDW-7_SOT363-6
PQ910 = DMP3099L-7_SOT23-3
PR4 PR104 PR105 PR114 PR119 PR120 PR208 PR210 PR312 PR402 PR406 PR412 PR422 PR423 PR427 PR504 PR602 PR603 PR606 PR607 PR609 PR614 PR616 PR620 PR625 PR659 PR671 PR679 PR804 PR806 PR807 PR810 PR815 PR816 PR819 PR820 PR828 PR833 PR835 PR836 PR901 PR906 PR907 PR913 PR918 PR919 PR922 PR923 PR926 PR930-PR932 PR937 PR938 RA35-RA37 RA45 RC37 RC41 RC61 RC62 RC64 RC170 RC171 RC173 RC211 RC214 RC221 RC228-RC231 RC235 RC244 RC289 RC290 RC295 RC296 RC300-RC303 RC307 RC308 RC325 RC327 RC328 RC337 RD29 RD66-RD68 RD70 RD72 RD74 RE32 RE59 RE275 RE290 RE305 RI15-RI31 RL3 RL7 RL34 RN99 RR17 RR18 RR21-RR23 RV662 RZ22 RZ23 RZ43 RZ56 RZ61 RZ64 RZ70 RZ85 RZ86 RZ89 RZ112 RZ118 = R0402_0OHM
PR13 PR921 RC194 = R_0805
PR100 PR111 PR304 R274 RA3 RA4 RC143 RC169 RC216 RC299 RC309 RC310 RD60 RD65 RL8 = R0603_0OHM
PR106 PR112 PR204 PR303 PR627 PR663 PR676 PR811 PR824 = R_1206
PR201 PR202 PR205 PR405 PR409 PR502 PR619 PR624 PR660 PR661 PR672 PR674 PR814 PR826 PR924 PR928 PR933 PR935 PR939 RC238 RL71-RL78 RZ72 RZ119 = R_0603
PR802 PR823 = R_1206_4P-D
PRP1 RPC1-RPC5 RPE2 RPE3 RPE5 RPE7-RPE13 RPV1 RPV2 = RP_0804_8P4R
PU1 = TS5A63157DCKR_SC70-6
PU100 = SY8286BRAC_QFN20_3X3
PU101 PU902 PU903 UC7 UC13 UC14 UE3 UE5 UL2 UZ6 UZ10 = TC7SH08FU_SSOP5
PU102 = SY8286CRAC_QFN20_3X3
PU201 = RT8207PGQW_WQFN20_3X3
PU301 = SYX196DQNC_QFN10_3X3
PU401 = TPS62134CRGT_QFN16_3X3
PU402 = TPS62134ARGT_QFN16_3X3
PU501 = SY8032ABC_SOT23-6
PU502 PU1500 = APL5930KAI-TRG_SO8
PU602 = ISL62883CHRTZ-T_TQFN40_5X5
PU603 PU605 = CSD97374CQ4M_SON8_3P5X4P5
PU606 = ISL95808HRZ-TS2378_DFN8_2X2
PU801 = BQ24715URUYR_WQFN28_4X4
PU901 = CD3301RHHR_QFN36_6X6
QA1 QC3 QE11 QR1 QV2 QV4 QV5 QV7 QV9-QV11 = L2N7002WT1G_SC-70-3
QE3-QE7 = MMBT3904WT1G_SC70-3
QV1 = AO6405_TSOP6
QV8 QZ1 QZ9 = LP2301ALT1G_SOT23-3
QZ4 = DDTA114EUA-7-F_SOT323-3
RA39 = R0805_0OHM
SW1 = SW_SS3-CMFTQR9_3P
SW3 = SW_SKRBAAE010_4P
T1-T6 T9-T17 T50 T51 T54 T55 T87-T89 T97-T99 T108 T113-T115 T120-T123 T126-T132 = TPC12
TL1 = MHPC_NS692417_24P
UA1 = ALC3235-CG_MQFN48_6X6
UC1 = SKL-U_BGA_1356P-T
UC5 = W25Q128FVSIQ_SO8
UC6 = W25Q64FVSSIQ_SO8
UC8 = 74CBTLV3126BQ_DHVQFN14_2P5X3
UC12 = 74AHC1G09GW_TSSOP5
UD1 UE4 = 74AUP1G07GW_TSSOP5
UE1 = ECE5048-LZY_DQFN132_11X11
UE2 = MEC5085-LZY_DQFN132_11X11
UI1 UI2 = SY6288D20AAC_SOT23-5
UI3 = PI5USB2544ZHEX_TQFN16_3X3
UL1 = WGI217LM-QPN9-A2_QFN48_6X6
UL4 = PI3L720ZHEX_TQFN42_9X3P5
UN1 = LNG2DMTR_LGA12_2X2
UN4 UN5 = PS8558BTQFN24GTR2-A_TQFN24_4X4
UN7 = PI3EQX6741STZDEX_TQFN20_4X4
UR2 = RTS5242-GR_QFN32_4X4
UV2 UV4 = AP2330W-7_SC59-3
UV8 = VMM3320BJGR_BGA_168P-NH
UV9 = W25X10BVSNIG_SO8
UV11 UV12 = PI3C3125LEX_TSSOP14
UV16 = PI3V713-AZLEX_TQFN32_6X3
UV24 = G524B1T11U_SOT23-5
UV26 = PS8338BQFN60GTR-A0_QFN60_5X9
UV28 UZ19-UZ21 UZ26 = TPS22961DNYR_WSON8
UV29 = APL5930QBI-TRG_TDFN10_3X3
UZ2-UZ5 = TPS22966DPUR_SON14_2X3
UZ8 UZ23 = AOZ1336_DFN8_2X2
UZ12 = NPCT650JAAYX_QFN32_5X5
YC1 = Y_X3G024000DC1H_4P
YC2 = Y_9H03200042_2P
YE1 = Y_Q13FC135000040_2P
YL1 = Y_7V25000034_4P
YV2 = Y_X1E000021042600_4P

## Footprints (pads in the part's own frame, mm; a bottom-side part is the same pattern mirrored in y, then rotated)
74AHC1G09GW_TSSOP5
  oval 0.381x1.346 smd: 1(0,0) 2(0.65,0) 3(1.3,0) 4(1.3,1.79) 5(0,1.79)
74AUP1G07GW_TSSOP5
  oval 0.381x1.346 smd: 1(0,0) 2(0.65,0) 3(1.3,0) 4(1.3,1.79) 5(0,1.79)
74CBTLV3126BQ_DHVQFN14_2P5X3
  oval 1.041x0.254 smd: 1(0,0) 7(2.95,0) 8(2.95,0.5) 14(0,0.5)
  oval 0.254x1.041 smd: 2(0.475,-0.975) 3(0.975,-0.975) 4(1.475,-0.975) 5(1.975,-0.975) 6(2.475,-0.975) 9(2.475,1.475) 10(1.975,1.475) 11(1.475,1.475) 12(0.975,1.475) 13(0.475,1.475)
  rect 1.499x0.991 smd: 15(1.475,0.25)
ACES_50207-00471-P01_4P-T
  oval 0.508x0.991 smd: 1(0,0) 2(-0.8,0) 3(-1.6,0) 4(-2.4,0)
  rect 1.194x1.702 smd: 5(-3.7,1.45) 6(1.3,1.45)
ACES_50271-0020N-001_2P
  oval 0.787x1.6 smd: 1(0,0) 2(1.25,0)
  rect 2.108x2.997 smd: 3(3.8,-2.9) 4(-2.55,-2.9)
ACES_50271-0040N-001_4P
  oval 0.787x1.6 smd: 1(0,0) 2(-1.25,0) 3(-2.5,0) 4(-3.75,0)
  rect 2.108x2.997 smd: 5(2.55,-2.9) 6(-6.3,-2.9)
ACES_50290-0050N-001_5P-T
  rect 0.838x7.01 smd: 1(0,0) 2(1.5,0) 3(3,0) 4(4.5,0) 5(6,0)
ACES_50398-04041-001_40P
  oval 0.254x1.295 smd: 1(0,0) 2(0.5,0) 3(1,0) 4(1.5,0) 5(2,0) 6(2.5,0) 7(3,0) 8(3.5,0) 9(4,0) 10(4.5,0) 11(5,0) 12(5.5,0) 13(6,0) 14(6.5,0) 15(7,0) 16(7.5,0) 17(8,0) 18(8.5,0) 19(9,0) 20(9.5,0) 21(10,0) 22(10.5,0) 23(11,0) 24(11.5,0) 25(12,0) 26(12.5,0) 27(13,0) 28(13.5,0) 29(14,0) 30(14.5,0) 31(15,0) 32(15.5,0) 33(16,0) 34(16.5,0) 35(17,0) 36(17.5,0) 37(18,0) 38(18.5,0) 39(19,0) 40(19.5,0)
  rect 1.194x3.2 smd: 41(-2.4,1.95) 45(21.9,1.95)
  rect 2.311x1.295 smd: 42(0.85,3.9) 43(9.75,3.9) 44(18.65,3.9)
ACES_50450-0067N-P01_6P
  oval 0.508x1.295 smd: 1(0,0) 2(0.8,0) 3(1.6,0) 4(2.4,0) 5(3.2,0) 6(4,0)
  rect 1.194x1.702 smd: 7(-1.3,1.3) 8(5.3,1.3)
ACES_50506-00841-P01_8P
  oval 0.305x0.889 smd: 1(0,0) 2(0.5,0) 3(1,0) 4(1.5,0) 5(2,0) 6(2.5,0) 7(3,0) 8(3.5,0)
  rect 0.991x2.007 smd: 9(-2.1,-3.05) 10(5.6,-3.05)
ACES_50506-01841-P01_18P-NPM
  oval 0.305x0.889 smd: 1(0,0) 2(0.5,0) 3(1,0) 4(1.5,0) 5(2,0) 6(2.5,0) 7(3,0) 8(3.5,0) 9(4,0) 10(4.5,0) 11(5,0) 12(5.5,0) 13(6,0) 14(6.5,0) 15(7,0) 16(7.5,0) 17(8,0) 18(8.5,0)
  rect 0.991x2.007 smd: 19(-2.1,-3.05) 20(10.6,-3.05)
ACES_50506-02041-P01_20P
  oval 0.305x0.889 smd: 1(0,0) 2(0.5,0) 3(1,0) 4(1.5,0) 5(2,0) 6(2.5,0) 7(3,0) 8(3.5,0) 9(4,0) 10(4.5,0) 11(5,0) 12(5.5,0) 13(6,0) 14(6.5,0) 15(7,0) 16(7.5,0) 17(8,0) 18(8.5,0) 19(9,0) 20(9.5,0)
  rect 0.991x2.007 smd: 21(-2.1,-3.05) 22(11.6,-3.05)
ACON_TARAV-9R1U91_9P
  round 1.295 hole 0.711: 1(0,0) 2(-2.5,0) 3(-4.5,0) 4(-7,0) 5(-7.5,-1.5) 6(-5.5,-1.5) 7(-3.5,-1.5) 8(-1.5,-1.5) 9(0.5,-1.5)
  oval 1.397x3.2 hole 0.787x2.591: 10(4.35,-2.43) 11(-11.35,-2.43)
  oval 1.397x2.311 hole 0.787x1.702: 12(-11.35,-9.23) 13(4.35,-9.23)
ALC3235-CG_MQFN48_6X6
  oval 0.203x0.889 smd: 1(0,0) 2(0.4,0) 3(0.8,0) 4(1.2,0) 5(1.6,0) 6(2,0) 7(2.4,0) 8(2.8,0) 9(3.2,0) 10(3.6,0) 11(4,0) 12(4.4,0) 25(4.4,6.1) 26(4,6.1) 27(3.6,6.1) 28(3.2,6.1) 29(2.8,6.1) 30(2.4,6.1) 31(2,6.1) 32(1.6,6.1) 33(1.2,6.1) 34(0.8,6.1) 35(0.4,6.1) 36(0,6.1)
  oval 0.889x0.203 smd: 13(5.25,0.85) 14(5.25,1.25) 15(5.25,1.65) 16(5.25,2.05) 17(5.25,2.45) 18(5.25,2.85) 19(5.25,3.25) 20(5.25,3.65) 21(5.25,4.05) 22(5.25,4.45) 23(5.25,4.85) 24(5.25,5.25) 37(-0.85,5.25) 38(-0.85,4.85) 39(-0.85,4.45) 40(-0.85,4.05) 41(-0.85,3.65) 42(-0.85,3.25) 43(-0.85,2.85) 44(-0.85,2.45) 45(-0.85,2.05) 46(-0.85,1.65) 47(-0.85,1.25) 48(-0.85,0.85)
  rect 4.394x4.394 smd: 49(2.2,3.05)
AO6405_TSOP6
  oval 0.508x1.473 smd: 1(0,0) 2(0.95,0) 3(1.9,0) 4(1.9,2.35) 5(0.95,2.35) 6(0,2.35)
AON6932A_DFN5X6-8-7
  oval 0.508x0.559 smd: 1(0,0)
  custom 0.475x0.475 smd: 2(1.905,0.7)
  oval 0.508x0.66 smd: 3(3.81,5.625) 4(2.54,5.625) 5(1.27,5.625) 6(0,5.625)
  rect 4.801x2.591 smd: 7(1.905,3.4)
AON7934_DFN3X3A8-10
  oval 0.457x0.508 smd: 1(0,0) 2(0.65,0) 3(1.3,0) 4(1.95,0) 5(1.95,2.76) 6(1.3,2.76) 7(0.65,2.76) 8(0,2.76)
  rect 2.54x1.041 smd: 9(0.975,1.813)
  rect 2.54x0.559 smd: 10(0.975,0.708)
AOZ1336_DFN8_2X2
  oval 0.254x0.787 smd: 1(0,0) 2(0.5,0) 3(1,0) 4(1.5,0) 5(1.5,2.2) 6(1,2.2) 7(0.5,2.2) 8(0,2.2)
  rect 1.499x0.889 smd: 9(0.75,1.1)
AP2330W-7_SC59-3
  oval 0.787x0.991 smd: 1(0,0) 2(-0.95,-2.4) 3(0.95,-2.4)
APL5930KAI-TRG_SO8
  oval 0.635x1.854 smd: 1(0,0) 2(1.27,0) 3(2.54,0) 4(3.81,0) 5(3.81,5.165) 6(2.54,5.165) 7(1.27,5.165) 8(0,5.165)
  rect 2.87x2.489 smd: 9(1.905,2.582)
APL5930QBI-TRG_TDFN10_3X3
  oval 0.254x0.889 smd: 1(0,0) 2(0.5,0) 3(1,0) 4(1.5,0) 5(2,0) 6(2,3.1) 7(1.5,3.1) 8(1,3.1) 9(0.5,3.1) 10(0,3.1)
  rect 2.438x1.575 smd: 11(1,1.55)
AZC199-02SPR7G_SOT23-3
  oval 1.016x1.524 smd: 1(0,0) 2(0.965,2.083) 3(-0.965,2.083)
BAT54CW_SOT323-3
  oval 0.711x0.889 smd: 1(0,0) 2(-0.65,-1.9) 3(0.65,-1.9)
BELLW_80148-4221_67P
  round 1.092 hole 1.092 unplated: (-0.75,-5.275)
  round 1.6 hole 1.6 unplated: (19.25,-5.275)
  oval 0.305x1.549 smd: 1(0,0) 2(0.25,-7.55) 3(0.5,0) 4(0.75,-7.55) 5(1,0) 6(1.25,-7.55) 7(1.5,0) 8(3.75,-7.55) 9(4,0) 10(4.25,-7.55) 11(4.5,0) 12(4.75,-7.55) 13(5,0) 14(5.25,-7.55) 15(5.5,0) 16(5.75,-7.55) 17(6,0) 18(6.25,-7.55) 19(6.5,0) 20(6.75,-7.55) 21(7,0) 22(7.25,-7.55) 23(7.5,0) 24(7.75,-7.55) 25(8,0) 26(8.25,-7.55) 27(8.5,0) 28(8.75,-7.55) 29(9,0) 30(9.25,-7.55) 31(9.5,0) 32(9.75,-7.55) 33(10,0) 34(10.25,-7.55) 35(10.5,0) 36(10.75,-7.55) 37(11,0) 38(11.25,-7.55) 39(11.5,0) 40(11.75,-7.55) 41(12,0) 42(12.25,-7.55) 43(12.5,0) 44(12.75,-7.55) 45(13,0) 46(13.25,-7.55) 47(13.5,0) 48(13.75,-7.55) 49(14,0) 50(14.25,-7.55) 51(14.5,0) 52(14.75,-7.55) 53(15,0) 54(15.25,-7.55) 55(15.5,0) 56(15.75,-7.55) 57(16,0) 58(16.25,-7.55) 59(16.5,0) 60(16.75,-7.55) 61(17,0) 62(17.25,-7.55) 63(17.5,0) 64(17.75,-7.55) 65(18,0) 66(18.25,-7.55) 67(18.5,0)
  rect 1.194x2.743 smd: 68(-1.1,-0.775) 69(19.6,-0.775)
BELLW_80149-4221_67P
  round 1.092 hole 1.092 unplated: (-0.75,-5.275)
  round 1.6 hole 1.6 unplated: (19.25,-5.275)
  oval 0.305x1.549 smd: 1(0,0) 2(0.25,-7.55) 3(0.5,0) 4(0.75,-7.55) 5(1,0) 6(1.25,-7.55) 7(1.5,0) 8(1.75,-7.55) 9(2,0) 10(2.25,-7.55) 11(2.5,0) 12(4.75,-7.55) 13(5,0) 14(5.25,-7.55) 15(5.5,0) 16(5.75,-7.55) 17(6,0) 18(6.25,-7.55) 19(6.5,0) 20(6.75,-7.55) 21(7,0) 22(7.25,-7.55) 23(7.5,0) 24(7.75,-7.55) 25(8,0) 26(8.25,-7.55) 27(8.5,0) 28(8.75,-7.55) 29(9,0) 30(9.25,-7.55) 31(9.5,0) 32(9.75,-7.55) 33(10,0) 34(10.25,-7.55) 35(10.5,0) 36(10.75,-7.55) 37(11,0) 38(11.25,-7.55) 39(11.5,0) 40(11.75,-7.55) 41(12,0) 42(12.25,-7.55) 43(12.5,0) 44(12.75,-7.55) 45(13,0) 46(13.25,-7.55) 47(13.5,0) 48(13.75,-7.55) 49(14,0) 50(14.25,-7.55) 51(14.5,0) 52(14.75,-7.55) 53(15,0) 54(15.25,-7.55) 55(15.5,0) 56(15.75,-7.55) 57(16,0) 58(16.25,-7.55) 59(16.5,0) 60(16.75,-7.55) 61(17,0) 62(17.25,-7.55) 63(17.5,0) 64(17.75,-7.55) 65(18,0) 66(18.25,-7.55) 67(18.5,0)
  rect 1.194x2.743 smd: 68(-1.1,-0.775) 69(19.6,-0.775)
BELLW_SD-80159-4221_67P-T
  round 1.092 hole 1.092 unplated: (-0.75,-5.275)
  round 1.6 hole 1.6 unplated: (19.25,-5.275)
  oval 0.305x1.549 smd: 1(0,0) 2(0.25,-7.55) 3(0.5,0) 4(0.75,-7.55) 5(1,0) 6(1.25,-7.55) 7(1.5,0) 8(1.75,-7.55) 9(2,0) 10(2.25,-7.55) 11(2.5,0) 12(2.75,-7.55) 13(3,0) 14(3.25,-7.55) 15(3.5,0) 16(3.75,-7.55) 17(4,0) 18(4.25,-7.55) 19(4.5,0) 20(4.75,-7.55) 21(5,0) 22(5.25,-7.55) 23(5.5,0) 24(5.75,-7.55) 25(6,0) 26(6.25,-7.55) 27(6.5,0) 28(6.75,-7.55) 29(7,0) 30(7.25,-7.55) 31(7.5,0) 32(7.75,-7.55) 33(8,0) 34(8.25,-7.55) 35(8.5,0) 36(8.75,-7.55) 37(9,0) 38(9.25,-7.55) 39(9.5,0) 40(9.75,-7.55) 41(10,0) 42(10.25,-7.55) 43(10.5,0) 44(10.75,-7.55) 45(11,0) 46(11.25,-7.55) 47(11.5,0) 48(11.75,-7.55) 49(12,0) 50(12.25,-7.55) 51(12.5,0) 52(12.75,-7.55) 53(13,0) 54(13.25,-7.55) 55(13.5,0) 56(13.75,-7.55) 57(14,0) 58(14.25,-7.55) 59(16.5,0) 60(16.75,-7.55) 61(17,0) 62(17.25,-7.55) 63(17.5,0) 64(17.75,-7.55) 65(18,0) 66(18.25,-7.55) 67(18.5,0)
  rect 1.194x2.743 smd: 68(-1.1,-0.775) 69(19.6,-0.775)
BQ24715URUYR_WQFN28_4X4
  oval 0.889x0.203 smd: 1(0,0) 2(0,-0.4) 3(0,-0.8) 4(0,-1.2) 5(0,-1.6) 6(0,-2) 7(0,-2.4) 15(4.1,-2.4) 16(4.1,-2) 17(4.1,-1.6) 18(4.1,-1.2) 19(4.1,-0.8) 20(4.1,-0.4) 21(4.1,0)
  oval 0.203x0.889 smd: 8(0.85,-3.25) 9(1.25,-3.25) 10(1.65,-3.25) 11(2.05,-3.25) 12(2.45,-3.25) 13(2.85,-3.25) 14(3.25,-3.25) 22(3.25,0.85) 23(2.85,0.85) 24(2.45,0.85) 25(2.05,0.85) 26(1.65,0.85) 27(1.25,0.85) 28(0.85,0.85)
  rect 2.591x2.591 smd: 29(2.05,-1.2)
C_0201
  rect 0.381x0.356 smd: 1(0,0) 2(0.584,0)
C_0402
  rect 0.508x0.559 smd: 1(0,0) 2(0.914,0)
C_0603
  rect 0.635x0.889 smd: 1(0,0) 2(1.397,0)
C_0805
  rect 0.813x1.397 smd: 1(0,0) 2(1.702,0)
C_1206
  rect 1.016x1.651 smd: 1(0,0) 2(2.667,0)
C_1808
  rect 1.041x2.311 smd: 1(0,0) 2(4.35,0)
C_B2
  rect 1.346x2.692 smd: 1(0,0) 2(-2.75,0)
C_B2-NPM
  rect 1.346x2.692 smd: 1(0,0) 2(-2.75,0)
C_D
  rect 2.388x2.896 smd: 1(0,0) 2(6.1,0)
C_D2
  rect 2.388x2.794 smd: 1(0,0) 2(6.4,0)
C_D3
  rect 2.388x2.794 smd: 1(0,0) 2(6.4,0)
CD3301RHHR_QFN36_6X6
  oval 0.254x1.194 smd: 1(0,0) 2(0.5,0) 3(1,0) 4(1.5,0) 5(2,0) 6(2.5,0) 7(3,0) 8(3.5,0) 9(4,0) 19(4,5.8) 20(3.5,5.8) 21(3,5.8) 22(2.5,5.8) 23(2,5.8) 24(1.5,5.8) 25(1,5.8) 26(0.5,5.8) 27(0,5.8)
  oval 1.194x0.254 smd: 10(4.9,0.9) 11(4.9,1.4) 12(4.9,1.9) 13(4.9,2.4) 14(4.9,2.9) 15(4.9,3.4) 16(4.9,3.9) 17(4.9,4.4) 18(4.9,4.9) 28(-0.9,4.9) 29(-0.9,4.4) 30(-0.9,3.9) 31(-0.9,3.4) 32(-0.9,2.9) 33(-0.9,2.4) 34(-0.9,1.9) 35(-0.9,1.4) 36(-0.9,0.9)
  rect 4.089x4.089 smd: 37(2,2.9)
CONCR_099BKAC19YBLCNF_19P
  round 0.813 hole 0.508: 1(0,0) 2(0.5,1.5) 3(1,0) 4(1.5,1.5) 5(2,0) 6(2.5,1.5) 7(3,0) 8(3.5,1.5) 9(4,0) 10(4.5,1.5) 11(5,0) 12(5.5,1.5) 13(6,0) 14(6.5,1.5) 15(7,0) 16(7.5,1.5) 17(8,0) 18(8.5,1.5) 19(9,0)
  oval 1.397x3.15 hole 0.787x2.54: 20(-2.75,0.9) 21(11.75,0.9)
  oval 1.803x2.794 hole 0.787x1.803: 22(-4.75,-6.08) 23(13.75,-6.08)
CSD97374CQ4M_SON8_3P5X4P5
  oval 0.203x0.889 smd: 1(0,0) 2(0.4,0) 3(0.8,0) 6(0.8,3.5) 7(0.4,3.5) 8(0,3.5)
  custom 0.225x0.225 smd: 4(2.2,0.262) 5(2.2,3.238)
  rect 4.039x2.21 smd: 9(1.6,1.75)
CYNTE_PCMB063T-1R0MS_2P
  rect 2.362x3.505 smd: 1(0,0) 2(6.05,0)
CYNTE_PCMB063T-3R3MS_2P
  rect 2.362x3.505 smd: 1(0,0) 2(6.05,0)
CYNTE_PCMC063T-1R5MN_2P
  rect 2.159x3.505 smd: 1(0,0) 2(5.85,0)
DB3J315E0L_SMINI3-F2-B3
  oval 0.889x0.787 smd: 1(0,0) 2(-0.65,-1.9) 3(0.65,-1.9)
DDTA114EUA-7-F_SOT323-3
  oval 0.813x0.914 smd: 1(0,0) 2(0.65,1.6) 3(-0.65,1.6)
DEREN_40-42251-01001RHF_10P-T
  oval 0.838x2.21 smd: 1(0,0.1) 2(1.5,0.1) 3(3,0.1) 4(4.5,0.1) 5(6,0.1) 6(7.5,0.1) 7(9,0.1) 8(10.5,0.1) 9(12,0.1) 10(13.5,0.1)
  custom 0.75x0.75 smd: 11(-3.4,-3.15) 12(16.9,-3.15)
DMN65D8LDW-7_SOT363-6
  oval 0.432x0.61 smd: 1(0,0) 2(0.65,0) 3(1.3,0) 4(1.3,1.9) 5(0.65,1.9) 6(0,1.9)
DMN65D8LW-7_SOT323-3
  oval 0.711x0.889 smd: 1(0,0) 2(-0.65,-1.9) 3(0.65,-1.9)
DMP3099L-7_SOT23-3
  oval 1.016x1.524 smd: 1(0,0) 2(0.965,2.083) 3(-0.965,2.083)
E-T_6705K-Y20N-00L_20P
  oval 0.305x1.092 smd: 1(0,0) 2(-0.5,0) 3(-1,0) 4(-1.5,0) 5(-2,0) 6(-2.5,0) 7(-3,0) 8(-3.5,0) 9(-4,0) 10(-4.5,0) 11(-5,0) 12(-5.5,0) 13(-6,0) 14(-6.5,0) 15(-7,0) 16(-7.5,0) 17(-8,0) 18(-8.5,0) 19(-9,0) 20(-9.5,0)
  rect 0.991x2.007 smd: 21(2.1,-3.15) 22(-11.6,-3.15)
E-T_6705K-Y26N-00L_26P
  oval 0.305x1.092 smd: 1(0,0) 2(0.5,0) 3(1,0) 4(1.5,0) 5(2,0) 6(2.5,0) 7(3,0) 8(3.5,0) 9(4,0) 10(4.5,0) 11(5,0) 12(5.5,0) 13(6,0) 14(6.5,0) 15(7,0) 16(7.5,0) 17(8,0) 18(8.5,0) 19(9,0) 20(9.5,0) 21(10,0) 22(10.5,0) 23(11,0) 24(11.5,0) 25(12,0) 26(12.5,0)
  rect 0.991x2.007 smd: 27(-2.1,-3.15) 28(14.6,-3.15)
ECE5048-LZY_DQFN132_11X11
  oval 0.279x0.737 smd: A1(0,0) A2(0.5,0) A3(1,0) A4(1.5,0) A5(2,0) A6(2.5,0) A7(3,0) A8(3.5,0) A9(4,0) A10(4.5,0) A11(5,0) A12(5.5,0) A13(6,0) A14(6.5,0) A15(7,0) A16(7.5,0) A33(7.5,10.9) A34(7,10.9) A35(6.5,10.9) A36(6,10.9) A37(5.5,10.9) A38(5,10.9) A39(4.5,10.9) A40(4,10.9) A41(3.5,10.9) A42(3,10.9) A43(2.5,10.9) A44(2,10.9) A45(1.5,10.9) A46(1,10.9) A47(0.5,10.9) A48(0,10.9)
  oval 0.737x0.279 smd: A17(9.2,1.7) A18(9.2,2.2) A19(9.2,2.7) A20(9.2,3.2) A21(9.2,3.7) A22(9.2,4.2) A23(9.2,4.7) A24(9.2,5.2) A25(9.2,5.7) A26(9.2,6.2) A27(9.2,6.7) A28(9.2,7.2) A29(9.2,7.7) A30(9.2,8.2) A31(9.2,8.7) A32(9.2,9.2) A49(-1.7,9.2) A50(-1.7,8.7) A51(-1.7,8.2) A52(-1.7,7.7) A53(-1.7,7.2) A54(-1.7,6.7) A55(-1.7,6.2) A56(-1.7,5.7) A57(-1.7,5.2) A58(-1.7,4.7) A59(-1.7,4.2) A60(-1.7,3.7) A61(-1.7,3.2) A62(-1.7,2.7) A63(-1.7,2.2) A64(-1.7,1.7)
  oval 0.318x0.61 smd: B1(-0.25,0.855) B2(0.25,0.855) B3(0.75,0.855) B4(1.25,0.855) B5(1.75,0.855) B6(2.25,0.855) B7(2.75,0.855) B8(3.25,0.855) B9(3.75,0.855) B10(4.25,0.855) B11(4.75,0.855) B12(5.25,0.855) B13(5.75,0.855) B14(6.25,0.855) B15(6.75,0.855) B16(7.25,0.855) B17(7.75,0.855) B35(7.75,10.045) B36(7.25,10.045) B37(6.75,10.045) B38(6.25,10.045) B39(5.75,10.045) B40(5.25,10.045) B41(4.75,10.045) B42(4.25,10.045) B43(3.75,10.045) B44(3.25,10.045) B45(2.75,10.045) B46(2.25,10.045) B47(1.75,10.045) B48(1.25,10.045) B49(0.75,10.045) B50(0.25,10.045) B51(-0.25,10.045)
  oval 0.61x0.318 smd: B18(8.345,1.45) B19(8.345,1.95) B20(8.345,2.45) B21(8.345,2.95) B22(8.345,3.45) B23(8.345,3.95) B24(8.345,4.45) B25(8.345,4.95) B26(8.345,5.45) B27(8.345,5.95) B28(8.345,6.45) B29(8.345,6.95) B30(8.345,7.45) B31(8.345,7.95) B32(8.345,8.45) B33(8.345,8.95) B34(8.345,9.45) B52(-0.845,9.45) B53(-0.845,8.95) B54(-0.845,8.45) B55(-0.845,7.95) B56(-0.845,7.45) B57(-0.845,6.95) B58(-0.845,6.45) B59(-0.845,5.95) B60(-0.845,5.45) B61(-0.845,4.95) B62(-0.845,4.45) B63(-0.845,3.95) B64(-0.845,3.45) B65(-0.845,2.95) B66(-0.845,2.45) B67(-0.845,1.95) B68(-0.845,1.45)
  rect 5.105x5.105 smd: C1(3.75,5.45)
FDMC6679AZ_MLP8-5
  oval 0.432x0.711 smd: 1(0,0) 2(0.65,0) 3(1.3,0) 4(1.95,0)
  custom 0.537x0.537 smd: 5(0.975,2.075)
FDS6679AZ-G_SO8
  oval 0.635x1.676 smd: 1(0,0) 2(1.27,0) 3(2.54,0) 4(3.81,0) 5(3.81,5.35) 6(2.54,5.35) 7(1.27,5.35) 8(0,5.35)
FDV301N-G_SOT23-3
  oval 1.016x1.524 smd: 1(0,0) 2(0.965,2.083) 3(-0.965,2.083)
FIDUCIAL_C40M80
  round 1.016 smd: 1(0,0)
FUTUR_061-D531-0207_15P
  round 0.965 hole 0.711: 1(0,0) 2(2.29,0) 3(4.58,0) 4(6.87,0) 5(9.16,0) 6(-1.145,0) 7(1.145,0) 8(3.435,0) 9(5.725,0) 10(8.015,0) 11(0,1.4) 12(2.29,1.4) 13(4.58,1.4) 14(6.87,1.4) 15(9.16,1.4)
  oval 1.397x2.159 hole 0.991x1.753: 16(14.63,0.9) 17(-5.47,0.9)
G524B1T11U_SOT23-5
  oval 0.533x1.194 smd: 1(0,0) 2(0.95,0) 3(1.9,0) 4(1.9,3) 5(0,3)
H_0P8N
  round 0.787 hole 0.787 unplated: (0,0)
H_0P9N
  round 0.889 hole 0.889 unplated: (0,0)
H_2P4
  round 2.896 hole 2.388: 1(0,0)
H_2P6N
  round 2.591 hole 2.591 unplated: (0,0)
H_3P0X2P0N
  oval 2.997x2.007 hole 2.997x2.007 unplated: (0,0)
H_3P2
  round 3.708 hole 3.2: 1(0,0)
H_3P3
  round 3.81 hole 3.302: 1(0,0)
H_3P8
  round 4.318 hole 3.81: 1(0,0)
HB_A531015-SCHR21_10P
  oval 0.305x0.889 smd: 1(0,0) 2(0.5,0) 3(1,0) 4(1.5,0) 5(2,0) 6(2.5,0) 7(3,0) 8(3.5,0) 9(4,0) 10(4.5,0)
  rect 0.991x2.007 smd: 11(6.6,-3.05) 12(-2.1,-3.05)
IMD2AT-108_SC74-6
  oval 0.508x1.473 smd: 1(0,0) 2(-0.95,0) 3(-1.9,0) 4(-1.9,2.55) 5(-0.95,2.55) 6(0,2.55)
INPAQ_MCM1012B900F06BP_4P
  rect 0.711x0.305 smd: 1(0,0) 2(1.25,0) 3(1.25,-0.5) 4(0,-0.5)
ISL62883CHRTZ-T_TQFN40_5X5
  oval 0.203x0.991 smd: 1(0,0) 2(0.4,0) 3(0.8,0) 4(1.2,0) 5(1.6,0) 6(2,0) 7(2.4,0) 8(2.8,0) 9(3.2,0) 10(3.6,0) 21(3.6,4.95) 22(3.2,4.95) 23(2.8,4.95) 24(2.4,4.95) 25(2,4.95) 26(1.6,4.95) 27(1.2,4.95) 28(0.8,4.95) 29(0.4,4.95) 30(0,4.95)
  oval 0.991x0.203 smd: 11(4.275,0.675) 12(4.275,1.075) 13(4.275,1.475) 14(4.275,1.875) 15(4.275,2.275) 16(4.275,2.675) 17(4.275,3.075) 18(4.275,3.475) 19(4.275,3.875) 20(4.275,4.275) 31(-0.675,4.275) 32(-0.675,3.875) 33(-0.675,3.475) 34(-0.675,3.075) 35(-0.675,2.675) 36(-0.675,2.275) 37(-0.675,1.875) 38(-0.675,1.475) 39(-0.675,1.075) 40(-0.675,0.675)
  rect 3.505x3.505 smd: 41(1.8,2.475)
ISL95808HRZ-TS2378_DFN8_2X2
  oval 0.254x0.787 smd: 1(0,0) 2(0.5,0) 3(1,0) 4(1.5,0) 5(1.5,2.2) 6(1,2.2) 7(0.5,2.2) 8(0,2.2)
  rect 1.549x0.889 smd: 9(0.75,1.1)
JAE_WD2F144WB5R400_144P
  oval 1.702x1.092 hole 1.702x1.092 unplated: (3,-4) (34.5,-4)
  oval 0.254x1.803 smd: 1(0,0) 2(0,-8) 3(0.5,0) 4(0.5,-8) 5(1,0) 6(1,-8) 7(1.5,0) 8(1.5,-8) 9(2,0) 10(2,-8) 11(2.5,0) 12(2.5,-8) 13(3,0) 14(3,-8) 15(3.5,0) 16(3.5,-8) 17(4,0) 18(4,-8) 19(4.5,0) 20(4.5,-8) 21(5,0) 22(5,-8) 23(5.5,0) 24(5.5,-8) 25(6,0) 26(6,-8) 27(6.5,0) 28(6.5,-8) 29(7,0) 30(7,-8) 31(7.5,0) 32(7.5,-8) 33(8,0) 34(8,-8) 35(8.5,0) 36(8.5,-8) 37(9,0) 38(9,-8) 39(9.5,0) 40(9.5,-8) 41(10,0) 42(10,-8) 43(10.5,0) 44(10.5,-8) 45(11,0) 46(11,-8) 47(11.5,0) 48(11.5,-8) 49(12,0) 50(12,-8) 51(13.5,0) 52(13.5,-8) 53(14,0) 54(14,-8) 55(14.5,0) 56(14.5,-8) 57(15,0) 58(15,-8) 59(15.5,0) 60(15.5,-8) 61(16,0) 62(16,-8) 63(16.5,0) 64(16.5,-8) 65(17,0) 66(17,-8) 67(17.5,0) 68(17.5,-8) 69(18,0) 70(18,-8) 71(18.5,0) 72(18.5,-8) 73(19,0) 74(19,-8) 75(19.5,0) 76(19.5,-8) 77(20,0) 78(20,-8) 79(20.5,0) 80(20.5,-8) 81(21,0) 82(21,-8) 83(21.5,0) 84(21.5,-8) 85(22,0) 86(22,-8) 87(22.5,0) 88(22.5,-8) 89(23,0) 90(23,-8) 91(23.5,0) 92(23.5,-8) 93(24,0) 94(24,-8) 95(25.5,0) 96(25.5,-8) 97(26,0) 98(26,-8) 99(26.5,0) 100(26.5,-8) 101(27,0) 102(27,-8) 103(27.5,0) 104(27.5,-8) 105(28,0) 106(28,-8) 107(28.5,0) 108(28.5,-8) 109(29,0) 110(29,-8) 111(29.5,0) 112(29.5,-8) 113(30,0) 114(30,-8) 115(30.5,0) 116(30.5,-8) 117(31,0) 118(31,-8) 119(31.5,0) 120(31.5,-8) 121(32,0) 122(32,-8) 123(32.5,0) 124(32.5,-8) 125(33,0) 126(33,-8) 127(33.5,0) 128(33.5,-8) 129(34,0) 130(34,-8) 131(34.5,0) 132(34.5,-8) 133(35,0) 134(35,-8) 135(35.5,0) 136(35.5,-8) 137(36,0) 138(36,-8) 139(36.5,0) 140(36.5,-8) 141(37,0) 142(37,-8) 143(37.5,0) 144(37.5,-8)
  oval 1.753x3.607 hole 0.991x2.845: 145(-5.425,-4) 152(42.925,-4)
  oval 1.905x1.702 hole 1.143x0.94: 146(-1.55,-5.725) 148(-1.55,-2.275) 149(39.05,-5.725) 151(39.05,-2.275)
  oval 1.702x2.667 hole 0.94x1.905: 147(-2.475,-4) 150(39.975,-4)
  oval 3.759x1.6 hole 2.997x0.838: 153(-3.75,-7.925) 156(41.25,-7.925) 161(-3.75,-0.075) 164(41.25,-0.075)
  oval 1.753x1.6 hole 0.991x0.838: 154(12.75,-7.925) 155(24.75,-7.925) 162(12.75,-0.075) 163(24.75,-0.075)
  round 1.753 hole 0.991: 157(0.75,-4) 160(36.75,-4)
  round 2.159 hole 1.397: 158(12.75,-4) 159(24.75,-4)
JUMP_43X39
  custom 0.191x0.191 smd: 1(0,0) 2(0.914,0)
JUMP_43X79
  custom 0.188x0.188 smd: 1(0,0) 2(1.1,0)
JUMP_43X118
  custom 0.187x0.187 smd: 1(0,0) 2(1.1,0)
JUMP_43X118-NPM
  custom 0.187x0.187 smd: 1(0,0) 2(1.1,0)
KC_FBMA-L11-4532158_2P-NPM
  rect 1.803x3.404 smd: 1(0,0) 2(3.8,0)
L2N7002WT1G_SC-70-3
  oval 0.711x0.889 smd: 1(0,0) 2(-0.65,-1.9) 3(0.65,-1.9)
L03ESDL5V0CC3-2_SOT23-3
  oval 1.016x1.524 smd: 1(0,0) 2(0.965,2.083) 3(-0.965,2.083)
L05ESDL5V0NA-4_SLP2510P8-10-9
  rect 0.203x0.686 smd: 1(0,0) 2(-0.5,0) 4(-1.5,0) 5(-2,0) 6(-2,-0.875) 7(-1.5,-0.875) 8(-0.5,-0.875) 9(0,-0.875)
  rect 0.406x1.549 smd: 3(-1,-0.437)
L30ESD24VC3-2_SOT23-3
  oval 1.016x1.524 smd: 1(0,0) 2(0.965,2.083) 3(-0.965,2.083)
LED_LTW-C193DC-C_2P
  rect 0.787x0.787 smd: 1(0,0) 2(1.5,0)
LNG2DMTR_LGA12_2X2
  oval 0.406x0.305 smd: 1(0,0) 4(0,-1.5) 7(1.602,-1.5) 10(1.602,0)
  oval 0.508x0.305 smd: 2(0.051,-0.5) 3(0.051,-1) 8(1.551,-1) 9(1.551,-0.5)
  oval 0.305x0.508 smd: 5(0.551,-1.5) 6(1.051,-1.5) 11(1.051,0) 12(0.551,0)
LOTES_ADDR0107-P005A_260P-T
  round 1.092 hole 1.092 unplated: (-67.775,-4.1)
  round 1.6 hole 1.6 unplated: (1.025,-4.1)
  oval 0.305x1.753 smd: 1(0,0) 2(-0.25,-8.2) 3(-0.5,0) 4(-0.75,-8.2) 5(-1,0) 6(-1.25,-8.2) 7(-1.5,0) 8(-1.75,-8.2) 9(-2,0) 10(-2.25,-8.2) 11(-2.5,0) 12(-2.75,-8.2) 13(-3,0) 14(-3.25,-8.2) 15(-3.5,0) 16(-3.75,-8.2) 17(-4,0) 18(-4.25,-8.2) 19(-4.5,0) 20(-4.75,-8.2) 21(-5,0) 22(-5.25,-8.2) 23(-5.5,0) 24(-5.75,-8.2) 25(-6,0) 26(-6.25,-8.2) 27(-6.5,0) 28(-6.75,-8.2) 29(-7,0) 30(-7.25,-8.2) 31(-7.5,0) 32(-7.75,-8.2) 33(-8,0) 34(-8.25,-8.2) 35(-8.5,0) 36(-8.75,-8.2) 37(-9,0) 38(-9.25,-8.2) 39(-9.5,0) 40(-9.75,-8.2) 41(-10,0) 42(-10.25,-8.2) 43(-10.5,0) 44(-10.75,-8.2) 45(-11,0) 46(-11.25,-8.2) 47(-11.5,0) 48(-11.75,-8.2) 49(-12,0) 50(-12.25,-8.2) 51(-12.5,0) 52(-12.75,-8.2) 53(-13,0) 54(-13.25,-8.2) 55(-13.5,0) 56(-13.75,-8.2) 57(-14,0) 58(-14.25,-8.2) 59(-14.5,0) 60(-14.75,-8.2) 61(-15,0) 62(-15.25,-8.2) 63(-15.5,0) 64(-15.75,-8.2) 65(-16,0) 66(-16.25,-8.2) 67(-16.5,0) 68(-16.75,-8.2) 69(-17,0) 70(-17.25,-8.2) 71(-17.5,0) 72(-17.75,-8.2) 73(-18,0) 74(-18.25,-8.2) 75(-18.5,0) 76(-18.75,-8.2) 77(-19,0) 78(-19.25,-8.2) 79(-19.5,0) 80(-19.75,-8.2) 81(-20,0) 82(-20.25,-8.2) 83(-20.5,0) 84(-20.75,-8.2) 85(-21,0) 86(-21.25,-8.2) 87(-21.5,0) 88(-21.75,-8.2) 89(-22,0) 90(-22.25,-8.2) 91(-22.5,0) 92(-22.75,-8.2) 93(-23,0) 94(-23.25,-8.2) 95(-23.5,0) 96(-23.75,-8.2) 97(-24,0) 98(-24.25,-8.2) 99(-24.5,0) 100(-24.75,-8.2) 101(-25,0) 102(-25.25,-8.2) 103(-25.5,0) 104(-25.75,-8.2) 105(-26,0) 106(-26.25,-8.2) 107(-26.5,0) 108(-26.75,-8.2) 109(-27,0) 110(-27.25,-8.2) 111(-27.5,0) 112(-27.75,-8.2) 113(-28,0) 114(-28.25,-8.2) 115(-28.5,0) 116(-28.75,-8.2) 117(-29,0) 118(-29.25,-8.2) 119(-29.5,0) 120(-29.75,-8.2) 121(-30,0) 122(-30.25,-8.2) 123(-30.5,0) 124(-30.75,-8.2) 125(-31,0) 126(-31.25,-8.2) 127(-31.5,0) 128(-31.75,-8.2) 129(-32,0) 130(-32.25,-8.2) 131(-32.5,0) 132(-32.75,-8.2) 133(-33,0) 134(-33.25,-8.2) 135(-33.5,0) 136(-33.75,-8.2) 137(-34,0) 138(-34.25,-8.2) 139(-34.5,0) 140(-34.75,-8.2) 141(-35,0) 142(-35.25,-8.2) 143(-35.5,0) 144(-35.75,-8.2) 145(-38,0) 146(-38.25,-8.2) 147(-38.5,0) 148(-38.75,-8.2) 149(-39,0) 150(-39.25,-8.2) 151(-39.5,0) 152(-39.75,-8.2) 153(-40,0) 154(-40.25,-8.2) 155(-40.5,0) 156(-40.75,-8.2) 157(-41,0) 158(-41.25,-8.2) 159(-41.5,0) 160(-41.75,-8.2) 161(-42,0) 162(-42.25,-8.2) 163(-42.5,0) 164(-42.75,-8.2) 165(-43,0) 166(-43.25,-8.2) 167(-43.5,0) 168(-43.75,-8.2) 169(-44,0) 170(-44.25,-8.2) 171(-44.5,0) 172(-44.75,-8.2) 173(-45,0) 174(-45.25,-8.2) 175(-45.5,0) 176(-45.75,-8.2) 177(-46,0) 178(-46.25,-8.2) 179(-46.5,0) 180(-46.75,-8.2) 181(-47,0) 182(-47.25,-8.2) 183(-47.5,0) 184(-47.75,-8.2) 185(-48,0) 186(-48.25,-8.2) 187(-48.5,0) 188(-48.75,-8.2) 189(-49,0) 190(-49.25,-8.2) 191(-49.5,0) 192(-49.75,-8.2) 193(-50,0) 194(-50.25,-8.2) 195(-50.5,0) 196(-50.75,-8.2) 197(-51,0) 198(-51.25,-8.2) 199(-51.5,0) 200(-51.75,-8.2) 201(-52,0) 202(-52.25,-8.2) 203(-52.5,0) 204(-52.75,-8.2) 205(-53,0) 206(-53.25,-8.2) 207(-53.5,0) 208(-53.75,-8.2) 209(-54,0) 210(-54.25,-8.2) 211(-54.5,0) 212(-54.75,-8.2) 213(-55,0) 214(-55.25,-8.2) 215(-55.5,0) 216(-55.75,-8.2) 217(-56,0) 218(-56.25,-8.2) 219(-56.5,0) 220(-56.75,-8.2) 221(-57,0) 222(-57.25,-8.2) 223(-57.5,0) 224(-57.75,-8.2) 225(-58,0) 226(-58.25,-8.2) 227(-58.5,0) 228(-58.75,-8.2) 229(-59,0) 230(-59.25,-8.2) 231(-59.5,0) 232(-59.75,-8.2) 233(-60,0) 234(-60.25,-8.2) 235(-60.5,0) 236(-60.75,-8.2) 237(-61,0) 238(-61.25,-8.2) 239(-61.5,0) 240(-61.75,-8.2) 241(-62,0) 242(-62.25,-8.2) 243(-62.5,0) 244(-62.75,-8.2) 245(-63,0) 246(-63.25,-8.2) 247(-63.5,0) 248(-63.75,-8.2) 249(-64,0) 250(-64.25,-8.2) 251(-64.5,0) 252(-64.75,-8.2) 253(-65,0) 254(-65.25,-8.2) 255(-65.5,0) 256(-65.75,-8.2) 257(-66,0) 258(-66.25,-8.2) 259(-66.5,0) 260(-66.75,-8.2)
  rect 3.505x4.597 smd: 261(-67.175,7.9) 262(0.425,7.9)
LOTES_AUSB0014-P003A_9P
  round 1.118 hole 0.711: 1(0,0) 2(-2.5,0) 3(-4.5,0) 4(-7,0) 5(-7.5,-1.5) 6(-5.5,-1.5) 7(-3.5,-1.5) 8(-1.5,-1.5) 9(0.5,-1.5)
  oval 1.549x2.769 hole 0.787x2.007: 10(-11.35,-1.59) 11(4.35,-1.59)
  oval 1.549x2.565 hole 0.787x1.803: 12(-11.35,-9.09) 13(4.35,-9.09)
LP2301ALT1G_SOT23-3
  oval 1.016x1.524 smd: 1(0,0) 2(0.965,2.083) 3(-0.965,2.083)
MAG_MLV-FY12N1R0M-O1L_2P
  rect 0.889x2.489 smd: 1(0,0) 2(2.6,0)
MAG_MMD06CZER15MG_4P
  custom 0.686x0.686 smd: 1(0,0) 4(8.509,0)
  rect 2.362x0.508 smd: 2(1.448,0) 3(7.061,0)
MAG_MMD-05CZ-R68M-X2L_2P
  rect 1.905x2.794 smd: 1(0,0) 2(4.1,0)
MAGLA_MMD-05CZ-1R0M-M7L_2P
  rect 1.905x2.794 smd: 1(0,0) 2(4.1,0)
MEC5085-LZY_DQFN132_11X11
  oval 0.279x0.711 smd: A1(0,0) A2(0.5,0) A3(1,0) A4(1.5,0) A5(2,0) A6(2.5,0) A7(3,0) A8(3.5,0) A9(4,0) A10(4.5,0) A11(5,0) A12(5.5,0) A13(6,0) A14(6.5,0) A15(7,0) A16(7.5,0) A33(7.5,10.9) A34(7,10.9) A35(6.5,10.9) A36(6,10.9) A37(5.5,10.9) A38(5,10.9) A39(4.5,10.9) A40(4,10.9) A41(3.5,10.9) A42(3,10.9) A43(2.5,10.9) A44(2,10.9) A45(1.5,10.9) A46(1,10.9) A47(0.5,10.9) A48(0,10.9)
  oval 0.711x0.279 smd: A17(9.2,1.7) A18(9.2,2.2) A19(9.2,2.7) A20(9.2,3.2) A21(9.2,3.7) A22(9.2,4.2) A23(9.2,4.7) A24(9.2,5.2) A25(9.2,5.7) A26(9.2,6.2) A27(9.2,6.7) A28(9.2,7.2) A29(9.2,7.7) A30(9.2,8.2) A31(9.2,8.7) A32(9.2,9.2) A49(-1.7,9.2) A50(-1.7,8.7) A51(-1.7,8.2) A52(-1.7,7.7) A53(-1.7,7.2) A54(-1.7,6.7) A55(-1.7,6.2) A56(-1.7,5.7) A57(-1.7,5.2) A58(-1.7,4.7) A59(-1.7,4.2) A60(-1.7,3.7) A61(-1.7,3.2) A62(-1.7,2.7) A63(-1.7,2.2) A64(-1.7,1.7)
  oval 0.305x0.61 smd: B1(-0.25,0.85) B2(0.25,0.85) B3(0.75,0.85) B4(1.25,0.85) B5(1.75,0.85) B6(2.25,0.85) B7(2.75,0.85) B8(3.25,0.85) B9(3.75,0.85) B10(4.25,0.85) B11(4.75,0.85) B12(5.25,0.85) B13(5.75,0.85) B14(6.25,0.85) B15(6.75,0.85) B16(7.25,0.85) B17(7.75,0.85) B35(7.75,10.05) B36(7.25,10.05) B37(6.75,10.05) B38(6.25,10.05) B39(5.75,10.05) B40(5.25,10.05) B41(4.75,10.05) B42(4.25,10.05) B43(3.75,10.05) B44(3.25,10.05) B45(2.75,10.05) B46(2.25,10.05) B47(1.75,10.05) B48(1.25,10.05) B49(0.75,10.05) B50(0.25,10.05) B51(-0.25,10.05)
  oval 0.61x0.305 smd: B18(8.35,1.45) B19(8.35,1.95) B20(8.35,2.45) B21(8.35,2.95) B22(8.35,3.45) B23(8.35,3.95) B24(8.35,4.45) B25(8.35,4.95) B26(8.35,5.45) B27(8.35,5.95) B28(8.35,6.45) B29(8.35,6.95) B30(8.35,7.45) B31(8.35,7.95) B32(8.35,8.45) B33(8.35,8.95) B34(8.35,9.45) B52(-0.85,9.45) B53(-0.85,8.95) B54(-0.85,8.45) B55(-0.85,7.95) B56(-0.85,7.45) B57(-0.85,6.95) B58(-0.85,6.45) B59(-0.85,5.95) B60(-0.85,5.45) B61(-0.85,4.95) B62(-0.85,4.45) B63(-0.85,3.95) B64(-0.85,3.45) B65(-0.85,2.95) B66(-0.85,2.45) B67(-0.85,1.95) B68(-0.85,1.45)
  rect 5.004x5.004 smd: C1(3.75,5.45)
